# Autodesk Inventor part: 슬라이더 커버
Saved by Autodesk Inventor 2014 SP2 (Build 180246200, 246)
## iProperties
Created: 2025-07
Part Number: 슬라이더 커버
Material: Generic
Document SubType Name: Modeling
Designer: Administrator
Density: 1 g/cm^3
Appearance: Default
Author: Administrator
Author: jhkim
Creation Date: 2025-06-11
Sending System: Autodesk Inventor 2026
Preprocessor: ST-DEVELOPER v20.1
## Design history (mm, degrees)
node "슬라이더 커버1"
node "솔리드1"
node "기준1"
